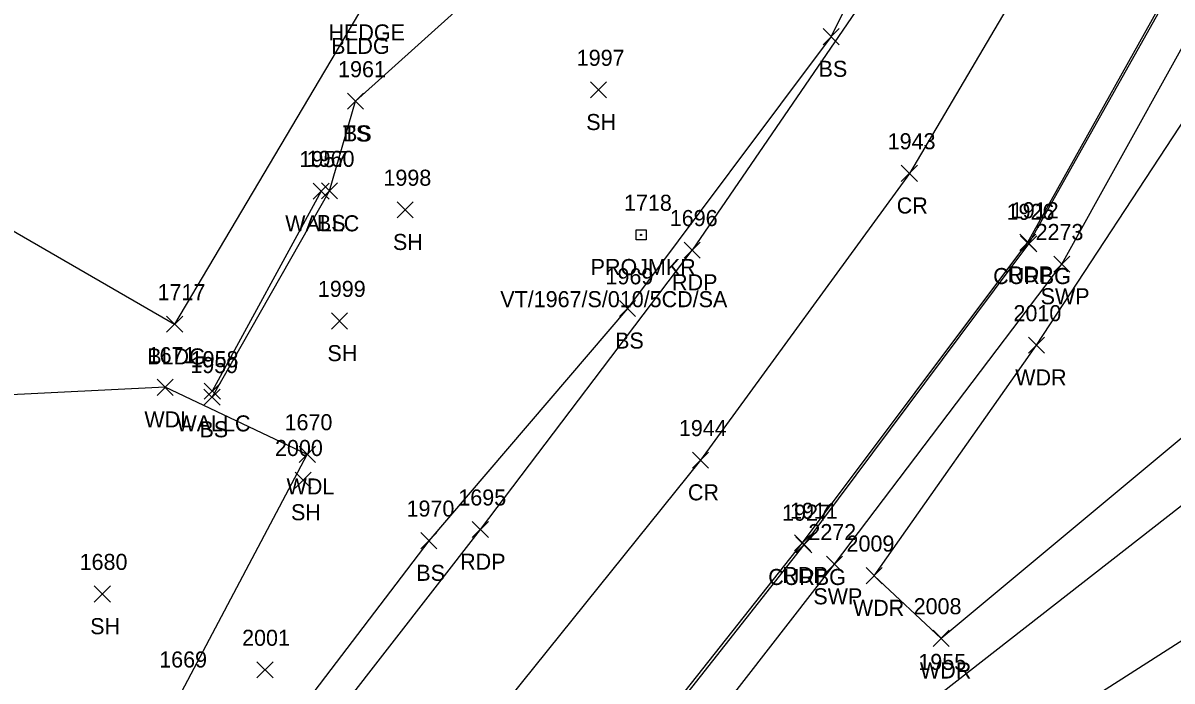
# Model space of a CAD drawing. Extents: x 462930 to 463548, y 29607 to 30453.
# Drawn here: x 463350.88 to 463394.45, y 30175.85 to 30200.82 of the extents above; entities that cross this region are included whole.
import ezdxf

# ---------------------------------------------------------------- set-up
doc = ezdxf.new("R2010")
doc.units = 0
for name, color, linetype in [('L_A', 7, 'Continuous'), ('L_I', 7, 'Continuous'), ('L_TIC', 7, 'Continuous'), ('LAWA', 7, 'Continuous'), ('LBC', 7, 'Continuous'), ('LELB', 7, 'Continuous'), ('LW', 7, 'Continuous'), ('P_A', 7, 'Continuous'), ('P_I', 7, 'Continuous'), ('P_TIC', 7, 'Continuous'), ('PET', 7, 'Continuous'), ('PRC', 7, 'Continuous'), ('R_A', 7, 'Continuous'), ('R_I', 7, 'Continuous'), ('R_TIC', 7, 'Continuous'), ('RC', 7, 'Continuous'), ('RDW', 7, 'Continuous'), ('RSW', 7, 'Continuous'), ('S_A', 7, 'Continuous'), ('S_C', 7, 'Continuous'), ('S_I', 7, 'Continuous'), ('SRM', 7, 'Continuous')]:
    doc.layers.add(name, color=color, linetype=linetype)

msp = doc.modelspace()

# ---------------------------------------------------------------- linework, layer by layer
at = {"layer": 'L_TIC'}
for points in [[(463381.219, 30199.995), (463381.829, 30200.605)], [(463381.829, 30199.995), (463381.219, 30200.605)], [(463372.396, 30197.974), (463373.006, 30198.584)], [(463373.006, 30197.974), (463372.396, 30198.584)], [(463363.187, 30197.542), (463363.797, 30198.152)], [(463363.797, 30197.542), (463363.187, 30198.152)], [(463363.187, 30197.542), (463363.797, 30198.152)], [(463363.797, 30197.542), (463363.187, 30198.152)], [(463361.88, 30194.131), (463362.49, 30194.741)], [(463362.49, 30194.131), (463361.88, 30194.741)], [(463362.196, 30194.142), (463362.806, 30194.752)], [(463362.806, 30194.142), (463362.196, 30194.752)], [(463365.066, 30193.423), (463365.676, 30194.033)], [(463365.676, 30193.423), (463365.066, 30194.033)], [(463373.504, 30189.682), (463374.114, 30190.292)], [(463374.114, 30189.682), (463373.504, 30190.292)], [(463356.327, 30189.08), (463356.937, 30189.69)], [(463356.937, 30189.08), (463356.327, 30189.69)], [(463362.581, 30189.205), (463363.191, 30189.815)], [(463363.191, 30189.205), (463362.581, 30189.815)], [(463389.006, 30188.283), (463389.616, 30188.893)], [(463389.616, 30188.283), (463389.006, 30188.893)], [(463355.967, 30186.689), (463356.577, 30187.299)], [(463356.577, 30186.689), (463355.967, 30187.299)], [(463357.744, 30186.315), (463358.354, 30186.925)], [(463358.354, 30186.315), (463357.744, 30186.925)], [(463357.756, 30186.538), (463358.366, 30187.148)], [(463358.366, 30186.538), (463357.756, 30187.148)], [(463361.358, 30184.145), (463361.968, 30184.755)], [(463361.968, 30184.145), (463361.358, 30184.755)], [(463361.201, 30183.167), (463361.811, 30183.777)], [(463361.811, 30183.167), (463361.201, 30183.777)], [(463365.968, 30180.868), (463366.578, 30181.478)], [(463366.578, 30180.868), (463365.968, 30181.478)], [(463382.849, 30179.54), (463383.459, 30180.15)], [(463383.459, 30179.54), (463382.849, 30180.15)], [(463353.586, 30178.844), (463354.196, 30179.454)], [(463354.196, 30178.844), (463353.586, 30179.454)], [(463385.392, 30177.162), (463386.002, 30177.772)], [(463386.002, 30177.162), (463385.392, 30177.772)], [(463359.754, 30175.965), (463360.364, 30176.575)], [(463360.364, 30175.965), (463359.754, 30176.575)]]:
    msp.add_lwpolyline(points, dxfattribs=at)
at = {"layer": 'LAWA'}
for points in [[(463387.88, 30168.775), (463397.819, 30177.75), (463407.759, 30184.507), (463409.113, 30187.695), (463404.765, 30189.586), (463395.481, 30185.625), (463385.697, 30177.467), (463383.154, 30179.845), (463389.311, 30188.588), (463395.273, 30197.676), (463398.338, 30200.205), (463401.253, 30207.173), (463406.706, 30214.979), (463411.487, 30213.228), (463413.614, 30212.548), (463416.075, 30212.295), (463420.44, 30211.542)], [(463334.191, 30153.632), (463326.241, 30157.391), (463319.877, 30160.227), (463314.478, 30162.732), (463317.175, 30171.812), (463324.684, 30170.939), (463329.084, 30171.282), (463333.083, 30171.461), (463343.25, 30171.173), (463352.596, 30169.581), (463356.899, 30175.447), (463361.663, 30184.45), (463356.272, 30186.994), (463347.611, 30186.575), (463333.194, 30190.781), (463330.167, 30185.817), (463328.348, 30182.689), (463321.007, 30182.589)]]:
    msp.add_lwpolyline(points, dxfattribs=at)
at = {"layer": 'LBC'}
for points in [[(463363.604, 30201.169), (463356.632, 30189.385)], [(463339.201, 30199.476), (463356.632, 30189.385)]]:
    msp.add_lwpolyline(points, dxfattribs=at)
at = {"layer": 'LELB'}
for points in [[(463363.492, 30197.847), (463368.625, 30202.477), (463377.077, 30211.035), (463383.848, 30217.818), (463391.133, 30225.22), (463391.469, 30222.327)], [(463391.469, 30222.327), (463388.015, 30213.37), (463381.524, 30200.3), (463373.809, 30189.987), (463366.273, 30181.173), (463359.853, 30172.726), (463354.448, 30169.466)], [(463358.049, 30186.62), (463362.501, 30194.447), (463363.492, 30197.847)]]:
    msp.add_lwpolyline(points, dxfattribs=at)
at = {"layer": 'LW'}
msp.add_lwpolyline([(463362.185, 30194.436), (463358.061, 30186.843)], dxfattribs=at)
at = {"layer": 'P_TIC'}
for points in [[(463384.187, 30194.808), (463384.797, 30195.418)], [(463384.797, 30194.808), (463384.187, 30195.418)], [(463375.955, 30191.893), (463376.565, 30192.503)], [(463376.565, 30191.893), (463375.955, 30192.503)], [(463388.681, 30192.19), (463389.291, 30192.8)], [(463389.291, 30192.19), (463388.681, 30192.8)], [(463376.268, 30183.922), (463376.878, 30184.532)], [(463376.878, 30183.922), (463376.268, 30184.532)], [(463367.92, 30181.289), (463368.53, 30181.899)], [(463368.53, 30181.289), (463367.92, 30181.899)], [(463380.134, 30180.784), (463380.744, 30181.394)], [(463380.744, 30180.784), (463380.134, 30181.394)]]:
    msp.add_lwpolyline(points, dxfattribs=at)
at = {"layer": 'PET'}
for points in [[(463357.128, 30146.779), (463364.23, 30160.089), (463372.211, 30170.687), (463380.439, 30181.089), (463388.986, 30192.495), (463395.438, 30204.072), (463399.65, 30216.413), (463402.389, 30229.411), (463403.525, 30242.02), (463404.007, 30246.74), (463403.926, 30248.538), (463404.123, 30251.434)], [(463384.995, 30204.976), (463376.26, 30192.198)], [(463357.576, 30167.469), (463361.27, 30172.626), (463368.225, 30181.594), (463376.26, 30192.198)]]:
    msp.add_lwpolyline(points, dxfattribs=at)
at = {"layer": 'PRC'}
msp.add_lwpolyline([(463399.789, 30246.987), (463397.991, 30230.027), (463395.304, 30217.172), (463391.095, 30206.312), (463384.492, 30195.113), (463376.573, 30184.227), (463367.848, 30173.371), (463360.659, 30162.372), (463353.283, 30149.309)], dxfattribs=at)
at = {"layer": 'R_TIC'}
for points in [[(463388.711, 30192.13), (463389.321, 30192.74)], [(463389.321, 30192.13), (463388.711, 30192.74)], [(463389.968, 30191.363), (463390.578, 30191.973)], [(463390.578, 30191.363), (463389.968, 30191.973)], [(463380.182, 30180.711), (463380.792, 30181.321)], [(463380.792, 30180.711), (463380.182, 30181.321)], [(463381.351, 30179.976), (463381.961, 30180.586)], [(463381.961, 30179.976), (463381.351, 30180.586)]]:
    msp.add_lwpolyline(points, dxfattribs=at)
at = {"layer": 'RC'}
msp.add_lwpolyline([(463403.888, 30243.164), (463403.731, 30243.164), (463403.598, 30241.759), (463402.492, 30229.375), (463399.74, 30216.359), (463395.506, 30204.018), (463389.016, 30192.435), (463380.487, 30181.016), (463372.297, 30170.609), (463364.316, 30160.034), (463357.246, 30146.767)], dxfattribs=at)
at = {"layer": 'RDW'}
msp.add_lwpolyline([(463370.611, 30158.273), (463377.737, 30164.866), (463387.605, 30172.767), (463398.297, 30179.61), (463406.605, 30184.823), (463404.673, 30188.349), (463395.336, 30182.896), (463385.655, 30175.354), (463377.627, 30169.204)], dxfattribs=at)
at = {"layer": 'RSW'}
msp.add_lwpolyline([(463365.586, 30159.156), (463373.394, 30169.643), (463381.656, 30180.281), (463390.273, 30191.668), (463396.887, 30203.599), (463401.229, 30215.977), (463404.093, 30229.321), (463404.817, 30241.819)], dxfattribs=at)
at = {"layer": 'SRM'}
msp.add_lwpolyline([(463374.129, 30192.968), (463374.511, 30192.968), (463374.511, 30192.586), (463374.129, 30192.586)], close=True, dxfattribs=at)
msp.add_circle((463374.32, 30192.777), 0.0254, dxfattribs=at)

# ---------------------------------------------------------------- texts
at = {"layer": 'L_A'}
for s, p in [('HEDGE', (463362.467, 30200.156)), ('BLDG', (463362.565, 30199.645)), ('BS', (463381.049, 30198.776)), ('SH', (463372.24, 30196.755)), ('TS', (463363.007, 30196.323)), ('BS', (463363.017, 30196.323)), ('WALLC', (463360.824, 30192.912)), ('BS', (463362.026, 30192.923)), ('SH', (463364.91, 30192.204)), ('BS', (463373.334, 30188.463)), ('SH', (463362.425, 30187.986)), ('BLDG', (463355.593, 30187.861)), ('WDR', (463388.507, 30187.064)), ('WDL', (463355.485, 30185.47)), ('WALLC', (463356.7, 30185.319)), ('BS', (463357.574, 30185.096)), ('WDL', (463360.876, 30182.926)), ('SH', (463361.045, 30181.948)), ('BS', (463365.798, 30179.649)), ('WDR', (463382.35, 30178.321)), ('SH', (463353.43, 30177.625)), ('WDR', (463384.893, 30175.943))]:
    msp.add_text(s, height=0.6096, dxfattribs=at).set_placement(p)
at = {"layer": 'L_I'}
for s, p in [('1997', (463371.88, 30199.193)), ('1961', (463362.83, 30198.761)), ('1961', (463362.83, 30198.761)), ('1957', (463361.364, 30195.35)), ('1960', (463361.639, 30195.361)), ('1998', (463364.55, 30194.642)), ('1969', (463372.971, 30190.901)), ('1717', (463355.984, 30190.299)), ('1999', (463362.063, 30190.424)), ('2010', (463388.44, 30189.502)), ('1671', (463355.61, 30187.908)), ('1959', (463357.226, 30187.534)), ('1958', (463357.24, 30187.757)), ('1670', (463360.801, 30185.364)), ('2000', (463360.438, 30184.386)), ('1970', (463365.426, 30182.087)), ('2009', (463382.11, 30180.759)), ('1680', (463353.029, 30180.063)), ('2008', (463384.655, 30178.381)), ('2001', (463359.19, 30177.184)), ('1669', (463356.047, 30176.361))]:
    msp.add_text(s, height=0.6096, dxfattribs=at).set_placement(p)
at = {"layer": 'P_A'}
for s, p in [('CR', (463384.014, 30193.589)), ('RDP', (463388.22, 30190.971)), ('RDP', (463375.494, 30190.674)), ('CR', (463376.095, 30182.703)), ('RDP', (463367.459, 30180.07)), ('RDP', (463379.673, 30179.565))]:
    msp.add_text(s, height=0.6096, dxfattribs=at).set_placement(p)
at = {"layer": 'P_I'}
for s, p in [('1943', (463383.671, 30196.027)), ('1912', (463388.338, 30193.409)), ('1696', (463375.408, 30193.112)), ('1944', (463375.752, 30185.141)), ('1695', (463367.39, 30182.508)), ('1911', (463379.964, 30182.003))]:
    msp.add_text(s, height=0.6096, dxfattribs=at).set_placement(p)
at = {"layer": 'R_A'}
for s, p in [('CURBG', (463387.67, 30190.911)), ('SWP', (463389.469, 30190.144)), ('CURBG', (463379.141, 30179.492)), ('SWP', (463380.852, 30178.757))]:
    msp.add_text(s, height=0.6096, dxfattribs=at).set_placement(p)
at = {"layer": 'R_I'}
for s, p in [('1926', (463388.178, 30193.349)), ('2273', (463389.279, 30192.582)), ('1927', (463379.666, 30181.93)), ('2272', (463380.662, 30181.195)), ('1955', (463384.834, 30176.268))]:
    msp.add_text(s, height=0.6096, dxfattribs=at).set_placement(p)
at = {"layer": 'S_A'}
msp.add_text('PROJMKR', height=0.6096, dxfattribs=at).set_placement((463372.407, 30191.253))
at = {"layer": 'S_C'}
msp.add_text('VT/1967/S/010/5CD/SA', height=0.6096, dxfattribs=at).set_placement((463368.98, 30190.034))
at = {"layer": 'S_I'}
msp.add_text('1718', height=0.6096, dxfattribs=at).set_placement((463373.672, 30193.691))

doc.saveas('drawing.dxf')
